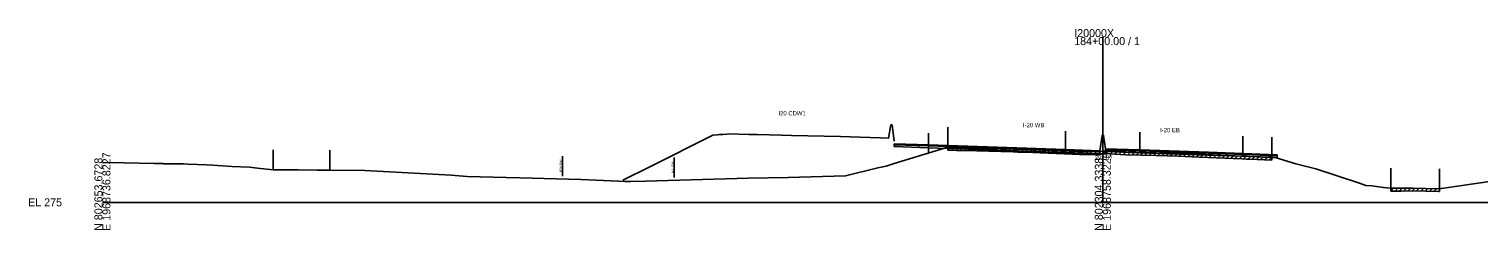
# Model space of a CAD drawing. Extents: x -4026 to 9638, y -10 to 19609.
# Drawn here: x 4974 to 5481, y 5490 to 5561 of the extents above; entities that cross this region are included whole.
import ezdxf

# ---------------------------------------------------------------- set-up
doc = ezdxf.new("R2010")
doc.units = 0
for name, color, linetype in [('Default', 7, 'Continuous'), ('RD_EX_Road', 7, 'Continuous'), ('RD_GPK_XS_Cell', 7, 'Continuous'), ('RD_PD_ALT1_TrvlWay', 7, 'Continuous'), ('RD_TX_Misc1', 7, 'Continuous'), ('RD_XS_Base', 7, 'Continuous'), ('RD_XS_ExGround', 7, 'Continuous'), ('RD_XS_ExPaveRet', 7, 'Continuous'), ('RD_XS_ExRW', 7, 'Continuous'), ('RD_XS_MedBWall', 7, 'Continuous'), ('RD_XS_NewRW', 7, 'Continuous'), ('RD_XS_Pave', 7, 'Continuous'), ('RD_XS_PaveOvlay', 7, 'Continuous'), ('RD_XS_TX_Elev_EX', 7, 'Continuous')]:
    doc.layers.add(name, color=color, linetype=linetype)

msp = doc.modelspace()

# ---------------------------------------------------------------- linework, layer by layer
at = {"layer": 'RD_EX_Road'}
for p, q in [((5295.73, 5526.28), (5295.73, 5519.28)), ((5409.2, 5522.79), (5409.2, 5515.79)), ((5059.78, 5518.37), (5059.78, 5511.37)), ((5079.58, 5518.31), (5079.58, 5511.31)), ((5450.75, 5511.94), (5450.75, 5504.94)), ((5467.76, 5511.75), (5467.76, 5504.75))]:
    msp.add_line(p, q, dxfattribs=at)
at = {"layer": 'RD_GPK_XS_Cell'}
for p, q in [((5350, 5500), (5350, 5557.85)), ((5000, 5500), (5350, 5500)), ((5350, 5500), (5700, 5500))]:
    msp.add_line(p, q, dxfattribs=at)
at = {"layer": 'RD_PD_ALT1_TrvlWay'}
for p, q in [((5289, 5524.23), (5289, 5517.23)), ((5337, 5524.95), (5337, 5517.95)), ((5363, 5524.53), (5363, 5517.53)), ((5399, 5523.19), (5399, 5516.19))]:
    msp.add_line(p, q, dxfattribs=at)
at = {"layer": 'RD_XS_Base'}
for points in [[(5277, 5520.18), (5277, 5519.51)], [(5289, 5519.77), (5277, 5520.18)], [(5277, 5519.51), (5289, 5519.1)], [(5337, 5518.14), (5313, 5518.96), (5289, 5519.77)], [(5289, 5519.77), (5289, 5519.1)], [(5289, 5519.77), (5289, 5519.77), (5289, 5519.1), (5289, 5519.1)], [(5289, 5519.1), (5313, 5518.29), (5337, 5517.47)], [(5337, 5517.47), (5337, 5518.14)], [(5349, 5517.67), (5337, 5518.14)], [(5337, 5517.47), (5349, 5517)], [(5349, 5517), (5349, 5517.67)], [(5351, 5517.76), (5351, 5518.43)], [(5351, 5518.43), (5363, 5518.01)], [(5363, 5517.34), (5351, 5517.76)], [(5363, 5517.34), (5363, 5518.01)], [(5363, 5518.01), (5387, 5517.2), (5399, 5516.79)], [(5399, 5516.12), (5387, 5516.53), (5363, 5517.34)], [(5399, 5516.79), (5399, 5516.79), (5399, 5516.12), (5399, 5516.12)], [(5399, 5516.12), (5399, 5516.79)], [(5399, 5516.79), (5411, 5516.31)], [(5411, 5515.64), (5399, 5516.12)], [(5411, 5516.31), (5411, 5515.64)]]:
    msp.add_lwpolyline(points, dxfattribs=at)
at = {"layer": 'RD_XS_ExGround'}
msp.add_lwpolyline([(5000, 5514), (5007.59, 5513.84), (5018.13, 5513.62), (5021.17, 5513.56), (5021.49, 5513.52), (5024.84, 5513.48), (5028.33, 5513.43), (5029.88, 5513.35), (5033.24, 5513.27), (5036.26, 5513.17), (5038.58, 5513.06), (5045.23, 5512.52), (5051.49, 5512.26), (5054.25, 5511.95), (5059.78, 5511.37), (5063.93, 5511.4), (5068.5, 5511.41), (5075.08, 5511.31), (5079.58, 5511.31), (5091.77, 5511.12), (5122.06, 5509.49), (5127.6, 5509.09), (5141.21, 5508.64), (5145.99, 5508.53), (5167.4, 5507.95), (5180.63, 5507.38), (5182.74, 5507.32), (5183.86, 5507.31), (5184.74, 5507.28), (5189.95, 5507.36), (5225.91, 5508.48), (5239.93, 5508.64), (5260.03, 5509.25), (5271.25, 5512.08), (5274.19, 5512.72), (5276.99, 5513.57), (5295.73, 5519.28), (5298.82, 5519.18), (5305.8, 5518.98), (5318.65, 5518.66), (5319.55, 5518.64), (5320.23, 5518.62), (5321.31, 5518.58), (5325.55, 5518.41), (5341.84, 5517.76), (5347.71, 5517.66), (5348.46, 5517.66), (5350.06, 5517.88), (5351.43, 5518.07), (5352.23, 5518.02), (5358.07, 5517.68), (5368.7, 5517.37), (5376.39, 5517.17), (5383.71, 5516.84), (5398.67, 5516.2), (5400.3, 5516.14), (5401.49, 5516.09), (5409.2, 5515.79), (5410.27, 5515.68), (5417.51, 5513.52), (5424.48, 5511.77), (5439.83, 5506.72), (5442.08, 5505.94), (5444.1, 5505.74), (5448.19, 5505.23), (5450.75, 5504.94), (5454.37, 5504.96), (5458.54, 5505.01), (5467.43, 5504.75), (5467.76, 5504.75), (5468.42, 5504.81), (5469.32, 5504.94), (5486.13, 5507.42)], dxfattribs=at)
at = {"layer": 'RD_XS_ExPaveRet'}
for p, q in [((5295.73, 5518.28), (5295.73, 5519.28)), ((5295.73, 5518.28), (5296.7, 5519.25)), ((5295.73, 5518.28), (5298.82, 5518.18)), ((5297.23, 5518.24), (5298.2, 5519.2)), ((5298.73, 5518.19), (5299.71, 5519.16)), ((5298.82, 5518.18), (5305.8, 5517.98)), ((5300.23, 5518.14), (5301.21, 5519.11)), ((5301.73, 5518.1), (5302.71, 5519.07)), ((5303.23, 5518.06), (5304.21, 5519.03)), ((5304.73, 5518.01), (5305.71, 5518.98)), ((5305.8, 5517.98), (5318.65, 5517.66)), ((5306.23, 5517.97), (5307.21, 5518.95)), ((5307.73, 5517.93), (5308.71, 5518.91)), ((5309.23, 5517.89), (5310.21, 5518.87)), ((5310.73, 5517.86), (5311.71, 5518.83)), ((5312.23, 5517.82), (5313.21, 5518.79)), ((5313.73, 5517.78), (5314.71, 5518.76)), ((5315.23, 5517.74), (5316.21, 5518.72)), ((5316.73, 5517.7), (5317.71, 5518.68)), ((5318.23, 5517.67), (5319.21, 5518.65)), ((5318.65, 5517.66), (5319.55, 5517.64)), ((5319.55, 5517.64), (5320.23, 5517.62)), ((5319.73, 5517.63), (5320.7, 5518.6)), ((5320.23, 5517.62), (5321.31, 5517.58)), ((5321.23, 5517.58), (5322.19, 5518.54)), ((5321.31, 5517.58), (5325.55, 5517.41)), ((5322.73, 5517.52), (5323.7, 5518.48)), ((5324.23, 5517.46), (5325.2, 5518.42)), ((5325.55, 5517.41), (5341.84, 5516.76)), ((5325.73, 5517.4), (5326.7, 5518.36)), ((5327.23, 5517.34), (5328.2, 5518.3)), ((5328.73, 5517.28), (5329.7, 5518.24)), ((5330.23, 5517.22), (5331.2, 5518.18)), ((5331.73, 5517.16), (5332.7, 5518.12)), ((5333.23, 5517.1), (5334.2, 5518.07)), ((5334.73, 5517.04), (5335.7, 5518.01)), ((5336.23, 5516.99), (5337.2, 5517.95)), ((5337.73, 5516.93), (5338.7, 5517.89)), ((5339.23, 5516.87), (5340.2, 5517.83)), ((5340.73, 5516.81), (5341.7, 5517.77)), ((5341.84, 5516.76), (5347.71, 5516.66)), ((5342.23, 5516.76), (5343.22, 5517.74)), ((5343.73, 5516.73), (5344.72, 5517.72)), ((5345.23, 5516.71), (5346.22, 5517.69)), ((5346.73, 5516.68), (5347.72, 5517.66)), ((5347.71, 5516.66), (5348.46, 5516.66)), ((5348.23, 5516.66), (5349.35, 5517.78)), ((5348.46, 5516.66), (5350.06, 5516.88)), ((5349.73, 5516.83), (5350.9, 5518)), ((5350.06, 5516.88), (5351.43, 5517.07)), ((5351.23, 5517.05), (5352.21, 5518.02)), ((5351.43, 5517.07), (5352.23, 5517.02)), ((5352.23, 5517.02), (5358.07, 5516.68)), ((5352.73, 5516.99), (5353.68, 5517.93)), ((5354.23, 5516.9), (5355.18, 5517.85)), ((5355.73, 5516.81), (5356.68, 5517.76)), ((5357.23, 5516.73), (5358.18, 5517.67)), ((5358.07, 5516.68), (5368.7, 5516.37)), ((5358.73, 5516.66), (5359.71, 5517.63)), ((5360.23, 5516.61), (5361.21, 5517.58)), ((5361.73, 5516.57), (5362.71, 5517.54)), ((5363.23, 5516.53), (5364.21, 5517.5)), ((5364.73, 5516.48), (5365.71, 5517.45)), ((5366.23, 5516.44), (5367.21, 5517.41)), ((5367.73, 5516.39), (5368.71, 5517.37)), ((5368.7, 5516.37), (5376.39, 5516.17)), ((5369.23, 5516.35), (5370.21, 5517.33)), ((5370.73, 5516.31), (5371.71, 5517.29)), ((5372.23, 5516.28), (5373.21, 5517.25)), ((5373.73, 5516.24), (5374.71, 5517.22)), ((5375.23, 5516.2), (5376.21, 5517.18)), ((5376.39, 5516.17), (5383.71, 5515.84)), ((5376.73, 5516.16), (5377.69, 5517.11)), ((5378.23, 5516.09), (5379.19, 5517.04)), ((5379.73, 5516.02), (5380.69, 5516.98)), ((5381.23, 5515.95), (5382.19, 5516.91)), ((5382.73, 5515.88), (5383.69, 5516.84)), ((5384.23, 5515.81), (5385.19, 5516.77)), ((5385.73, 5515.75), (5386.69, 5516.71)), ((5387.23, 5515.69), (5388.19, 5516.64)), ((5388.73, 5515.62), (5389.69, 5516.58)), ((5390.23, 5515.56), (5391.19, 5516.52)), ((5391.73, 5515.49), (5392.69, 5516.45)), ((5393.23, 5515.43), (5394.19, 5516.39)), ((5394.73, 5515.37), (5395.69, 5516.32)), ((5396.23, 5515.3), (5397.19, 5516.26)), ((5397.73, 5515.24), (5398.69, 5516.2)), ((5399.23, 5515.18), (5400.2, 5516.14)), ((5400.73, 5515.12), (5401.7, 5516.09)), ((5402.23, 5515.07), (5403.2, 5516.03)), ((5403.73, 5515.01), (5404.7, 5515.97)), ((5405.23, 5514.95), (5406.2, 5515.91)), ((5383.71, 5515.84), (5398.67, 5515.2)), ((5398.67, 5515.2), (5400.3, 5515.14)), ((5400.3, 5515.14), (5401.49, 5515.09)), ((5401.49, 5515.09), (5409.2, 5514.79)), ((5406.73, 5514.89), (5407.7, 5515.85)), ((5408.23, 5514.83), (5409.2, 5515.79)), ((5409.2, 5515.79), (5409.2, 5514.79)), ((5450.75, 5503.94), (5451.76, 5504.94)), ((5450.75, 5503.94), (5450.75, 5504.94)), ((5450.75, 5503.94), (5454.37, 5503.96)), ((5452.25, 5503.95), (5453.26, 5504.95)), ((5453.75, 5503.96), (5454.76, 5504.96)), ((5454.37, 5503.96), (5458.54, 5504.01)), ((5455.25, 5503.97), (5456.26, 5504.98)), ((5456.75, 5503.99), (5457.76, 5505)), ((5458.25, 5504.01), (5459.23, 5504.99)), ((5458.54, 5504.01), (5467.43, 5503.75)), ((5459.75, 5503.98), (5460.72, 5504.95)), ((5461.25, 5503.93), (5462.22, 5504.9)), ((5462.75, 5503.89), (5463.72, 5504.86)), ((5464.25, 5503.84), (5465.22, 5504.81)), ((5465.75, 5503.8), (5466.72, 5504.77)), ((5467.43, 5503.75), (5467.76, 5503.75)), ((5467.76, 5504.75), (5467.76, 5503.75))]:
    msp.add_line(p, q, dxfattribs=at)
at = {"layer": 'RD_XS_ExRW'}
msp.add_line((5200, 5508.67), (5200, 5515.67), dxfattribs=at)
at = {"layer": 'RD_XS_MedBWall'}
for points in [[(5349, 5518), (5349.75, 5523.43), (5350.25, 5523.43), (5351, 5518.76)], [(5349, 5517), (5349, 5518)], [(5351, 5517), (5349, 5517)], [(5351, 5518.76), (5351, 5517)]]:
    msp.add_lwpolyline(points, dxfattribs=at)
at = {"layer": 'RD_XS_NewRW'}
msp.add_line((5161, 5509.12), (5161, 5516.12), dxfattribs=at)
at = {"layer": 'RD_XS_Pave'}
for points in [[(5182.04, 5507.76), (5191.49, 5512.49), (5213.55, 5523.52), (5215.17, 5523.65), (5215.83, 5523.7), (5216.32, 5523.74), (5217.05, 5523.8), (5218.48, 5523.91), (5219.05, 5523.96), (5226.19, 5523.78), (5229.05, 5523.72), (5237.62, 5523.51), (5241.05, 5523.43), (5258.2, 5523.02), (5265.05, 5522.85), (5272.19, 5522.57), (5275.05, 5522.45), (5275.8, 5527.12), (5276.3, 5527.12), (5277.05, 5521.45)], [(5277, 5520.35), (5289, 5519.94)], [(5277, 5520.18), (5277, 5520.35)], [(5289, 5519.77), (5277, 5520.18)], [(5289, 5519.94), (5289, 5519.94), (5289, 5519.77), (5289, 5519.77)], [(5289, 5519.77), (5289, 5519.94)], [(5289, 5519.94), (5313, 5519.13), (5337, 5518.31)], [(5337, 5518.14), (5313, 5518.96), (5289, 5519.77)], [(5337, 5518.31), (5349, 5517.84)], [(5337, 5518.14), (5337, 5518.31)], [(5349, 5517.67), (5337, 5518.14)], [(5349, 5517.84), (5349, 5517.67)], [(5363, 5518.18), (5351, 5518.6)], [(5351, 5518.6), (5351, 5518.43)], [(5351, 5518.43), (5363, 5518.01)], [(5399, 5516.96), (5387, 5517.37), (5363, 5518.18)], [(5363, 5518.18), (5363, 5518.01)], [(5363, 5518.01), (5387, 5517.2), (5399, 5516.79)], [(5399, 5516.96), (5399, 5516.96), (5399, 5516.79), (5399, 5516.79)], [(5399, 5516.79), (5399, 5516.96)], [(5399, 5516.96), (5411, 5516.48)], [(5411, 5516.31), (5399, 5516.79)], [(5411, 5516.48), (5411, 5516.31)]]:
    msp.add_lwpolyline(points, dxfattribs=at)
at = {"layer": 'RD_XS_PaveOvlay'}
for points in [[(5277, 5520.52), (5289, 5520.11)], [(5277, 5520.35), (5277, 5520.52)], [(5289, 5519.94), (5277, 5520.35)], [(5289, 5520.11), (5313, 5519.29), (5337, 5518.48)], [(5289, 5519.94), (5289, 5520.11)], [(5289, 5520.11), (5289, 5520.11), (5289, 5519.94), (5289, 5519.94)], [(5337, 5518.31), (5313, 5519.13), (5289, 5519.94)], [(5337, 5518.48), (5337, 5518.31)], [(5337, 5518.48), (5349, 5518)], [(5349, 5517.84), (5337, 5518.31)], [(5349, 5518), (5349, 5517.84)], [(5363, 5518.35), (5351, 5518.76)], [(5351, 5518.76), (5351, 5518.6)], [(5351, 5518.6), (5363, 5518.18)], [(5399, 5517.12), (5387, 5517.53), (5363, 5518.35)], [(5363, 5518.35), (5363, 5518.18)], [(5363, 5518.18), (5387, 5517.37), (5399, 5516.96)], [(5399, 5516.96), (5399, 5517.12)], [(5399, 5517.12), (5411, 5516.64)], [(5399, 5517.12), (5399, 5517.12), (5399, 5516.96), (5399, 5516.96)], [(5411, 5516.48), (5399, 5516.96)], [(5411, 5516.64), (5411, 5516.48)]]:
    msp.add_lwpolyline(points, dxfattribs=at)

# ---------------------------------------------------------------- texts
at = {"layer": 'Default'}
msp.add_text('-', height=0.0001, dxfattribs=at).set_placement((5000, 5500))
at = {"layer": 'RD_GPK_XS_Cell'}
for s, p in [('184+00.00 / 1', (5340, 5555.05)), ('I20000X', (5340, 5557.85)), ('EL 275', (4974, 5498.6))]:
    msp.add_text(s, height=2.8, dxfattribs=at).set_placement(p)
for s, p in [('E 1968736.8227', (5002.8, 5490)), ('E 1968758.3225', (5352.8, 5490)), ('N 802653.6728', (5000, 5490)), ('N 802304.3338', (5350, 5490))]:
    msp.add_text(s, height=2.8, rotation=90, dxfattribs=at).set_placement(p)
at = {"layer": 'RD_TX_Misc1'}
for s, p in [('I20 CDW1', (5236.52, 5530.43)), ('I-20 WB', (5322.06, 5526.29)), ('I-20 EB', (5370.06, 5524.53))]:
    msp.add_text(s, height=1.5, dxfattribs=at).set_placement(p)
at = {"layer": 'RD_XS_ExRW'}
msp.add_text('EX. R/W ', height=0.75, rotation=90, dxfattribs=at).set_placement((5199.75, 5510.35))
at = {"layer": 'RD_XS_NewRW'}
msp.add_text('NEW R/W ', height=0.75, rotation=90, dxfattribs=at).set_placement((5160.75, 5510.27))
at = {"layer": 'RD_XS_TX_Elev_EX'}
msp.add_text('292.87', height=1.5, dxfattribs=at).set_placement((5347.11, 5514.87))

doc.saveas('drawing.dxf')
